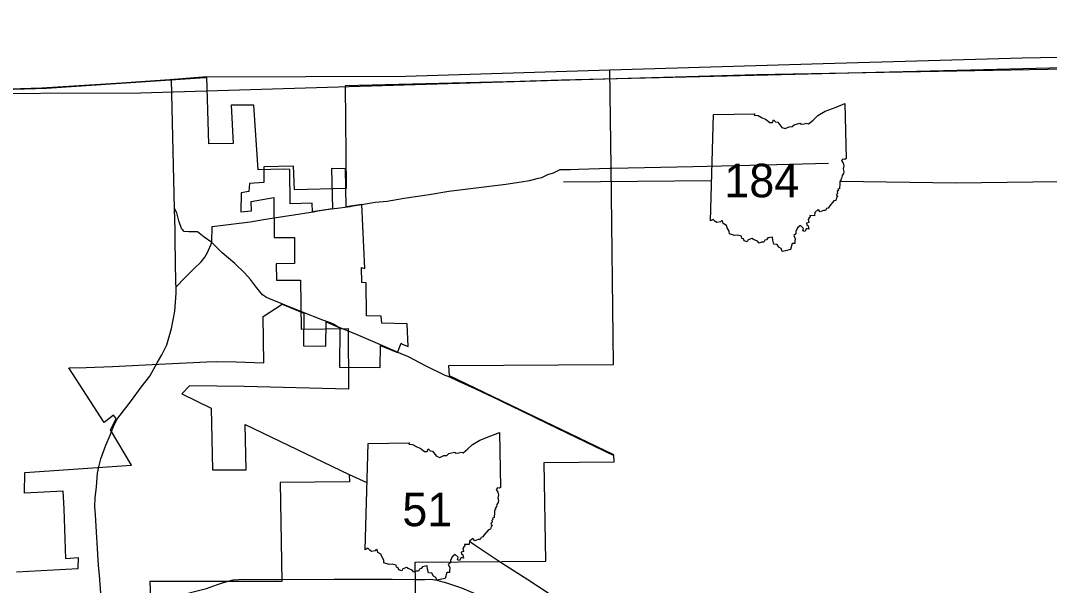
# Model space of a CAD drawing. Extents: x -232 to 448, y 619 to 1059.
# Drawn here: x 128.82 to 157.16, y 944.57 to 960.13 of the extents above; entities that cross this region are included whole.
import ezdxf

# ---------------------------------------------------------------- set-up
doc = ezdxf.new("R2010")
doc.units = 0
doc.layers.add('Default', color=7, linetype='Continuous')

msp = doc.modelspace()

# ---------------------------------------------------------------- linework, layer by layer
at = {"layer": 'Default'}
for p, q in [((147.824, 954.61), (147.906, 957.539)), ((147.824, 954.61), (147.906, 957.539)), ((135.801, 954.152), (136.365, 954.155)), ((136.365, 954.155), (136.369, 953.437)), ((136.369, 953.437), (135.856, 953.434)), ((135.856, 953.434), (135.866, 952.978)), ((135.866, 952.978), (136.531, 952.981)), ((136.624, 952.075), (136.616, 951.172)), ((137.231, 951.164), (137.24, 951.831)), ((137.615, 951.663), (137.601, 950.587)), ((139.472, 951.778), (138.768, 951.792)), ((136.616, 951.172), (137.231, 951.164)), ((139.201, 950.988), (139.307, 951.249)), ((137.601, 950.587), (138.729, 950.578)), ((138.311, 945.552), (138.393, 948.481)), ((138.311, 945.552), (138.393, 948.481)), ((130.411, 945.333), (130.069, 945.308))]:
    msp.add_line(p, q, dxfattribs=at)
for points in [[(145.054, 958.769), (150.927, 958.948), (156.407, 959.102), (171.427, 959.378), (185.934, 959.863), (198.796, 960.129)], [(191.559, 959.664), (178.631, 959.398), (164.124, 958.912), (149.104, 958.636), (143.624, 958.482), (132.12, 958.132), (126.614, 958.11), (126.592, 958.099), (122.234, 957.803), (110.103, 957.439)], [(106.941, 957.63), (115.861, 957.858), (129.538, 958.269), (129.538, 958.269), (133.907, 958.565), (133.928, 958.575), (139.422, 958.598), (145.054, 958.769)], [(142.542, 939.966), (142.53, 940.597), (143.197, 940.588), (143.174, 942.551), (142.47, 942.55), (142.445, 943.886), (140.432, 943.857), (140.597, 943.564), (139.374, 943.542), (139.361, 944.072), (139.707, 944.078), (139.685, 945.215), (143.284, 945.238), (143.246, 947.957), (145.167, 947.976), (145.165, 948.173), (140.633, 950.343), (140.619, 950.627), (145.149, 950.658), (145.086, 956.091), (145.054, 958.769)], [(154.62, 958.754), (149.028, 958.616)], [(159.881, 958.884), (157.886, 958.834), (154.62, 958.754)], [(133.947, 958.576), (132.929, 958.499), (131.465, 958.399), (129.408, 958.265), (127.029, 958.193)], [(133.059, 954.95), (132.976, 958.502), (132.972, 958.502)], [(136.232, 956.03), (136.065, 956.041), (135.36, 956.02), (135.246, 957.796), (134.622, 957.798), (134.678, 956.745), (134.001, 956.731), (133.947, 958.576)], [(143.718, 958.485), (142.569, 958.448), (137.764, 958.336)], [(149.028, 958.616), (146.405, 958.551), (143.718, 958.485)], [(137.764, 958.336), (137.792, 955.503), (136.365, 955.467), (136.338, 956.117)], [(147.906, 957.539), (149.042, 957.558), (149.025, 957.522), (149.132, 957.515), (149.246, 957.452), (149.342, 957.413), (149.46, 957.32), (149.53, 957.321), (149.56, 957.397), (149.614, 957.338), (149.678, 957.328), (149.789, 957.187), (149.88, 957.157), (149.99, 957.205), (150.072, 957.213), (150.132, 957.26), (150.288, 957.301), (150.331, 957.277), (150.414, 957.282), (150.455, 957.3), (150.527, 957.283), (150.654, 957.39), (150.784, 957.516), (150.985, 957.634), (151.285, 957.746), (151.522, 957.847), (151.556, 956.327)], [(147.906, 957.539), (149.042, 957.558), (149.025, 957.522), (149.132, 957.515), (149.246, 957.452), (149.342, 957.413), (149.46, 957.32), (149.53, 957.321), (149.56, 957.397), (149.614, 957.338), (149.678, 957.328), (149.789, 957.187), (149.88, 957.157), (149.99, 957.205), (150.072, 957.213), (150.132, 957.26), (150.288, 957.301), (150.331, 957.277), (150.414, 957.282), (150.455, 957.3), (150.527, 957.283), (150.654, 957.39), (150.784, 957.516), (150.985, 957.634), (151.285, 957.746), (151.522, 957.847), (151.556, 956.327)], [(145.054, 956.06), (145.103, 956.061), (147.343, 956.106), (149.294, 956.155), (151.076, 956.202)], [(151.556, 956.327), (151.521, 956.305), (151.467, 956.315), (151.43, 956.273), (151.475, 956.202), (151.497, 956.127), (151.478, 956.044), (151.497, 955.975), (151.484, 955.918), (151.45, 955.861), (151.438, 955.807), (151.409, 955.75), (151.411, 955.718), (151.383, 955.693), (151.388, 955.598), (151.374, 955.545), (151.379, 955.499), (151.334, 955.488), (151.345, 955.45), (151.316, 955.421), (151.322, 955.371), (151.29, 955.339), (151.321, 955.275), (151.296, 955.255), (151.275, 955.178), (151.217, 955.162), (151.102, 955.02), (151.061, 954.967), (151.015, 954.953), (150.99, 954.898), (150.933, 954.898), (150.848, 954.86), (150.793, 954.925), (150.696, 954.846), (150.685, 954.755), (150.563, 954.758), (150.567, 954.712), (150.54, 954.698), (150.515, 954.652), (150.53, 954.57), (150.472, 954.549), (150.479, 954.501), (150.516, 954.472), (150.532, 954.381), (150.472, 954.399), (150.422, 954.322), (150.37, 954.34), (150.387, 954.406), (150.301, 954.484), (150.219, 954.421), (150.176, 954.321), (150.176, 954.253), (150.115, 954.213), (150.154, 954.117), (150.147, 954.052), (150.148, 953.99), (150.071, 953.992), (150.025, 953.824)], [(151.556, 956.327), (151.521, 956.305), (151.467, 956.315), (151.43, 956.273), (151.475, 956.202), (151.497, 956.127), (151.478, 956.044), (151.497, 955.975), (151.484, 955.918), (151.45, 955.861), (151.438, 955.807), (151.409, 955.75), (151.411, 955.718), (151.383, 955.693), (151.388, 955.598), (151.374, 955.545), (151.379, 955.499), (151.334, 955.488), (151.345, 955.45), (151.316, 955.421), (151.322, 955.371), (151.29, 955.339), (151.321, 955.275), (151.296, 955.255), (151.275, 955.178), (151.217, 955.162), (151.102, 955.02), (151.061, 954.967), (151.015, 954.953), (150.99, 954.898), (150.933, 954.898), (150.848, 954.86), (150.793, 954.925), (150.696, 954.846), (150.685, 954.755), (150.563, 954.758), (150.567, 954.712), (150.54, 954.698), (150.515, 954.652), (150.53, 954.57), (150.472, 954.549), (150.479, 954.501), (150.516, 954.472), (150.532, 954.381), (150.472, 954.399), (150.422, 954.322), (150.37, 954.34), (150.387, 954.406), (150.301, 954.484), (150.219, 954.421), (150.176, 954.321), (150.176, 954.253), (150.115, 954.213), (150.154, 954.117), (150.147, 954.052), (150.148, 953.99), (150.071, 953.992), (150.025, 953.824)], [(136.338, 956.117), (135.516, 956.097), (135.516, 955.669), (135.125, 955.641), (135.106, 955.426), (134.894, 955.389), (134.888, 954.858), (135.181, 954.886), (135.171, 955.151), (135.794, 955.253)], [(136.854, 955.1), (136.25, 955.085), (136.232, 956.03)], [(137.789, 954.996), (137.774, 956.049), (137.387, 956.054)], [(137.387, 956.054), (137.414, 954.944)], [(143.089, 955.788), (143.174, 955.81), (143.343, 955.889), (143.503, 955.938), (143.646, 956.008)], [(143.646, 956.008), (143.68, 956.024), (143.968, 956.032)], [(143.968, 956.032), (144.185, 956.038)], [(144.185, 956.038), (145.054, 956.06)], [(138.217, 955.064), (138.585, 955.125), (138.913, 955.154), (139.384, 955.239), (140.073, 955.342), (140.62, 955.429), (142.184, 955.621)], [(142.184, 955.621), (142.611, 955.687)], [(142.611, 955.687), (142.841, 955.723), (143.089, 955.788)], [(143.775, 955.685), (147.855, 955.726)], [(151.4, 955.706), (154.583, 955.662), (165.199, 955.801)], [(135.794, 955.253), (135.801, 954.152)], [(137.414, 954.944), (136.859, 954.86), (136.854, 955.1)], [(137.468, 954.957), (137.896, 955.013)], [(138.345, 951.998), (138.338, 952.904), (138.22, 952.918), (138.214, 953.327), (138.301, 953.305), (138.222, 955.065), (137.789, 954.996)], [(137.896, 955.013), (137.971, 955.023), (138.217, 955.064)], [(133.074, 954.355), (133.059, 954.95)], [(133.274, 954.383), (133.256, 954.403), (133.183, 954.618), (133.125, 954.835), (133.059, 954.95)], [(134.095, 954.455), (135.144, 954.587), (135.508, 954.654), (136.095, 954.741), (136.47, 954.797), (136.694, 954.833), (136.881, 954.864)], [(136.881, 954.864), (137.009, 954.885), (137.313, 954.936), (137.468, 954.957)], [(134.09, 954.014), (134.095, 954.455)], [(150.025, 953.824), (149.893, 953.791), (149.801, 953.772), (149.768, 953.849), (149.702, 953.889), (149.659, 953.966), (149.565, 953.976), (149.542, 954.082), (149.532, 954.168), (149.403, 954.146), (149.367, 954.094), (149.321, 954.08), (149.295, 954.027), (149.232, 954.023), (149.165, 953.998), (149.121, 954.05), (149.011, 954.102), (148.962, 954.128), (148.859, 954.087), (148.837, 954.037), (148.755, 954.059), (148.735, 954.114), (148.686, 954.131), (148.675, 954.189), (148.568, 954.22), (148.487, 954.208), (148.343, 954.255), (148.335, 954.331), (148.286, 954.425), (148.26, 954.49), (148.17, 954.54), (148.151, 954.617), (148.122, 954.614), (148.096, 954.583), (147.995, 954.569), (147.955, 954.6), (147.898, 954.654), (147.824, 954.61)], [(150.025, 953.824), (149.893, 953.791), (149.801, 953.772), (149.768, 953.849), (149.702, 953.889), (149.659, 953.966), (149.565, 953.976), (149.542, 954.082), (149.532, 954.168), (149.403, 954.146), (149.367, 954.094), (149.321, 954.08), (149.295, 954.027), (149.232, 954.023), (149.165, 953.998), (149.121, 954.05), (149.011, 954.102), (148.962, 954.128), (148.859, 954.087), (148.837, 954.037), (148.755, 954.059), (148.735, 954.114), (148.686, 954.131), (148.675, 954.189), (148.568, 954.22), (148.487, 954.208), (148.343, 954.255), (148.335, 954.331), (148.286, 954.425), (148.26, 954.49), (148.17, 954.54), (148.151, 954.617), (148.122, 954.614), (148.096, 954.583), (147.995, 954.569), (147.955, 954.6), (147.898, 954.654), (147.824, 954.61)], [(133.1, 952.902), (133.081, 954.084), (133.074, 954.355)], [(133.69, 954.309), (133.685, 954.312), (133.456, 954.311), (133.325, 954.324), (133.274, 954.383)], [(134.09, 954.014), (133.874, 954.168), (133.69, 954.309)], [(133.102, 952.794), (133.345, 953.041), (133.603, 953.299), (133.791, 953.482), (133.894, 953.617), (133.971, 953.743), (134.09, 954.014)], [(135.933, 952.364), (135.724, 952.449), (135.598, 952.506), (135.48, 952.573), (135.317, 952.774), (135.15, 953), (135, 953.172), (134.721, 953.435), (134.375, 953.733), (134.09, 954.014)], [(132.386, 950.355), (132.583, 950.7), (132.715, 950.921), (132.846, 951.203), (132.977, 951.65), (133.069, 952.124), (133.102, 952.621), (133.102, 952.794), (133.1, 952.902)], [(136.531, 952.981), (136.545, 951.627)], [(135.517, 950.706), (135.502, 951.978), (136.022, 952.315), (136.624, 952.075)], [(136.793, 952.017), (136.173, 952.267), (135.933, 952.364)], [(137.148, 951.879), (136.884, 951.981), (136.793, 952.017)], [(138.768, 951.792), (138.754, 951.991), (138.345, 951.998)], [(136.545, 951.627), (137.843, 951.646), (137.848, 949.981)], [(137.352, 951.801), (137.148, 951.879)], [(137.24, 951.831), (137.615, 951.663)], [(138.797, 951.168), (138.712, 951.205), (138.07, 951.488), (137.622, 951.67), (137.54, 951.706), (137.453, 951.762), (137.352, 951.801)], [(139.492, 951.151), (139.472, 951.778)], [(138.729, 950.578), (138.734, 951.18)], [(138.734, 951.18), (139.201, 950.988)], [(139.3, 950.952), (138.797, 951.168)], [(139.307, 951.249), (139.331, 951.22)], [(139.331, 951.22), (139.492, 951.151)], [(140.518, 950.355), (139.971, 950.625), (139.501, 950.866), (139.3, 950.952)], [(130.152, 950.567), (130.625, 950.576)], [(131.296, 948.863), (131.456, 949.174), (131.38, 949.26), (131.123, 949.062), (130.152, 950.567)], [(130.625, 950.576), (131.354, 950.604), (132.813, 950.68), (133.946, 950.727), (134.21, 950.744), (134.757, 950.735), (135.517, 950.706)], [(131.345, 948.862), (131.378, 948.948), (131.475, 949.142), (131.656, 949.379), (131.873, 949.67), (132.146, 950.037), (132.378, 950.341), (132.386, 950.355)], [(141.357, 949.976), (141.338, 949.986), (140.875, 950.203), (140.648, 950.312), (140.542, 950.343), (140.518, 950.355)], [(137.848, 949.981), (134.978, 950.056), (133.47, 950.067), (133.262, 949.849)], [(142.239, 949.559), (142.003, 949.673), (141.357, 949.976)], [(133.262, 949.849), (134.074, 949.459)], [(134.074, 949.459), (134.11, 947.759)], [(145.17, 948.144), (143.347, 949.022), (142.306, 949.526), (142.239, 949.559)], [(130.988, 947.88), (131.028, 948.062), (131.166, 948.435), (131.288, 948.709), (131.345, 948.862)], [(131.876, 947.882), (131.296, 948.863)], [(135.037, 947.76), (135.005, 949.009)], [(135.005, 949.009), (137.869, 947.627), (137.88, 947.431)], [(138.393, 948.481), (139.529, 948.5), (139.512, 948.465), (139.619, 948.457), (139.733, 948.395), (139.829, 948.355), (139.947, 948.262), (140.017, 948.263), (140.047, 948.34), (140.101, 948.281), (140.165, 948.27), (140.276, 948.13), (140.367, 948.1), (140.477, 948.148), (140.559, 948.156), (140.619, 948.203), (140.775, 948.244), (140.818, 948.219), (140.901, 948.224), (140.942, 948.242), (141.014, 948.226), (141.141, 948.333), (141.271, 948.458), (141.472, 948.577), (141.772, 948.689), (142.009, 948.789), (142.043, 947.269)], [(138.393, 948.481), (139.529, 948.5), (139.512, 948.465), (139.619, 948.457), (139.733, 948.395), (139.829, 948.355), (139.947, 948.262), (140.017, 948.263), (140.047, 948.34), (140.101, 948.281), (140.165, 948.27), (140.276, 948.13), (140.367, 948.1), (140.477, 948.148), (140.559, 948.156), (140.619, 948.203), (140.775, 948.244), (140.818, 948.219), (140.901, 948.224), (140.942, 948.242), (141.014, 948.226), (141.141, 948.333), (141.271, 948.458), (141.472, 948.577), (141.772, 948.689), (142.009, 948.789), (142.043, 947.269)], [(129.994, 947.173), (128.932, 947.114), (128.938, 947.687), (131.876, 947.882)], [(130.99, 944.853), (130.969, 945.123), (130.881, 946.516), (130.868, 946.748), (130.879, 946.986), (130.907, 947.288), (130.941, 947.666), (130.988, 947.88)], [(134.11, 947.759), (135.037, 947.76)], [(137.88, 947.431), (135.967, 947.405)], [(135.967, 947.405), (136.015, 944.681)], [(138.363, 947.4), (137.876, 947.623), (137.869, 947.627)], [(130.069, 945.308), (130.019, 946.687), (129.994, 947.173)], [(142.043, 947.269), (142.008, 947.248), (141.954, 947.258), (141.917, 947.215), (141.963, 947.144), (141.984, 947.069), (141.965, 946.986), (141.984, 946.918), (141.971, 946.861), (141.937, 946.804), (141.925, 946.75), (141.896, 946.693), (141.898, 946.661), (141.87, 946.635), (141.875, 946.54), (141.861, 946.487), (141.866, 946.442), (141.821, 946.43), (141.832, 946.393), (141.803, 946.364), (141.809, 946.314), (141.777, 946.282), (141.808, 946.218), (141.783, 946.198), (141.762, 946.12), (141.704, 946.105), (141.589, 945.963), (141.548, 945.909), (141.502, 945.896), (141.477, 945.841), (141.42, 945.84), (141.335, 945.802), (141.28, 945.868), (141.183, 945.789), (141.172, 945.698), (141.05, 945.701), (141.054, 945.654), (141.027, 945.641), (141.002, 945.595), (141.017, 945.512), (140.96, 945.492), (140.966, 945.444), (141.003, 945.415), (141.019, 945.323), (140.959, 945.342), (140.909, 945.265), (140.858, 945.283), (140.874, 945.348), (140.788, 945.426), (140.706, 945.364), (140.663, 945.264), (140.663, 945.196), (140.602, 945.155), (140.641, 945.06), (140.634, 944.994), (140.635, 944.932), (140.558, 944.934), (140.512, 944.766)], [(142.043, 947.269), (142.008, 947.248), (141.954, 947.258), (141.917, 947.215), (141.963, 947.144), (141.984, 947.069), (141.965, 946.986), (141.984, 946.918), (141.971, 946.861), (141.937, 946.804), (141.925, 946.75), (141.896, 946.693), (141.898, 946.661), (141.87, 946.635), (141.875, 946.54), (141.861, 946.487), (141.866, 946.442), (141.821, 946.43), (141.832, 946.393), (141.803, 946.364), (141.809, 946.314), (141.777, 946.282), (141.808, 946.218), (141.783, 946.198), (141.762, 946.12), (141.704, 946.105), (141.589, 945.963), (141.548, 945.909), (141.502, 945.896), (141.477, 945.841), (141.42, 945.84), (141.335, 945.802), (141.28, 945.868), (141.183, 945.789), (141.172, 945.698), (141.05, 945.701), (141.054, 945.654), (141.027, 945.641), (141.002, 945.595), (141.017, 945.512), (140.96, 945.492), (140.966, 945.444), (141.003, 945.415), (141.019, 945.323), (140.959, 945.342), (140.909, 945.265), (140.858, 945.283), (140.874, 945.348), (140.788, 945.426), (140.706, 945.364), (140.663, 945.264), (140.663, 945.196), (140.602, 945.155), (140.641, 945.06), (140.634, 944.994), (140.635, 944.932), (140.558, 944.934), (140.512, 944.766)], [(143.987, 943.951), (143.381, 944.34), (142.789, 944.725), (142.086, 945.181), (141.31, 945.696), (141.182, 945.78)], [(140.512, 944.766), (140.38, 944.734), (140.288, 944.715), (140.255, 944.791), (140.189, 944.831), (140.146, 944.908), (140.052, 944.919), (140.03, 945.024), (140.019, 945.11), (139.89, 945.089), (139.854, 945.037), (139.808, 945.023), (139.782, 944.97), (139.719, 944.965), (139.652, 944.94), (139.608, 944.992), (139.498, 945.044), (139.449, 945.071), (139.346, 945.029), (139.324, 944.98), (139.242, 945.002), (139.222, 945.057), (139.173, 945.073), (139.162, 945.132), (139.055, 945.163), (138.974, 945.15), (138.83, 945.197), (138.822, 945.274), (138.773, 945.368), (138.747, 945.433), (138.657, 945.482), (138.638, 945.559), (138.609, 945.557), (138.583, 945.526), (138.482, 945.511), (138.442, 945.543), (138.385, 945.597), (138.311, 945.552)], [(140.512, 944.766), (140.38, 944.734), (140.288, 944.715), (140.255, 944.791), (140.189, 944.831), (140.146, 944.908), (140.052, 944.919), (140.03, 945.024), (140.019, 945.11), (139.89, 945.089), (139.854, 945.037), (139.808, 945.023), (139.782, 944.97), (139.719, 944.965), (139.652, 944.94), (139.608, 944.992), (139.498, 945.044), (139.449, 945.071), (139.346, 945.029), (139.324, 944.98), (139.242, 945.002), (139.222, 945.057), (139.173, 945.073), (139.162, 945.132), (139.055, 945.163), (138.974, 945.15), (138.83, 945.197), (138.822, 945.274), (138.773, 945.368), (138.747, 945.433), (138.657, 945.482), (138.638, 945.559), (138.609, 945.557), (138.583, 945.526), (138.482, 945.511), (138.442, 945.543), (138.385, 945.597), (138.311, 945.552)], [(130.409, 945.04), (130.411, 945.333)], [(128.708, 944.948), (130.065, 945.021)], [(130.065, 945.021), (130.409, 945.04)], [(131.138, 942.647), (131.072, 943.744), (130.99, 944.853)], [(132.38, 944.682), (132.423, 943.545), (132.075, 943.541), (132.078, 943.003), (133.254, 943.048), (133.105, 943.337), (135.151, 943.353)], [(136.015, 944.681), (132.38, 944.682)], [(132.818, 944.175), (133.069, 944.27), (133.944, 944.492), (134.245, 944.598), (134.383, 944.65), (134.537, 944.689), (134.675, 944.726), (134.97, 944.744), (135.833, 944.734), (137.454, 944.748), (139.058, 944.744), (139.679, 944.739)], [(139.679, 944.739), (139.952, 944.736), (140.119, 944.744), (140.287, 944.721), (140.553, 944.65), (140.965, 944.508), (141.264, 944.375), (141.496, 944.276), (141.745, 944.17), (141.848, 944.133)]]:
    msp.add_lwpolyline(points, dxfattribs=at)

# ---------------------------------------------------------------- texts
for s, p in [('184', (148.205, 955.263)), ('51', (139.335, 946.205))]:
    msp.add_text(s, height=0.9234, dxfattribs=at).set_placement(p)

doc.saveas('drawing.dxf')
